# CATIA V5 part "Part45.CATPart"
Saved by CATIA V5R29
Part number: Main case of rod
Revision: ANY
Definition: UNKNOWN
Nomenclature: Main case of rod
Source: Unknown
Bounding box of the stored display mesh (mm): x -41.99 to 41.99, y -18 to 33, z -22 to 22
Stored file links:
  C:\Users\Administrator\Desktop\프로젝트\Gripper\Part45.CATPart
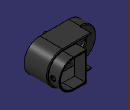
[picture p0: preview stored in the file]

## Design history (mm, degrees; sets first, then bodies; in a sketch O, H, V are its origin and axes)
Body1 "Fillet2" (main body)
  Solid1: solid without history
Body2 "Fillet5"
  Solid2: solid without history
